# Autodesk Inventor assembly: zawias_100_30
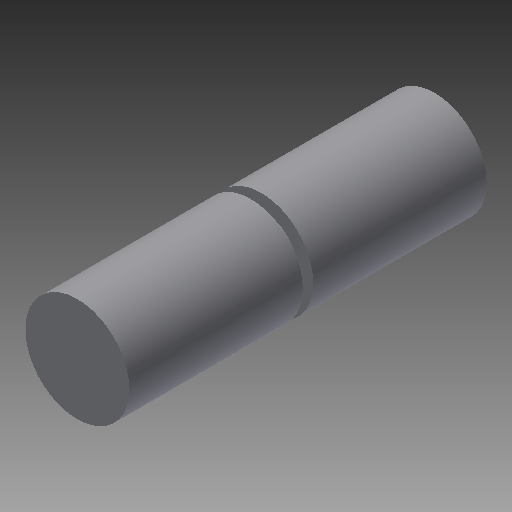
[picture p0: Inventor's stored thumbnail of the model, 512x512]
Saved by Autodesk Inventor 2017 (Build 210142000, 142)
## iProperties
Created: 2020-09
Part Number: zawias_100_30
Document SubType Name: Assembly
Designer: WindowsX
Mass: 68.0469 g
Surface Area: 175.301 cm^2
Volume: 68.0469 cm^3
Density: 1 g/cm^3
Author: WindowsX
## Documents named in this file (3)
- C:\Users\WindowsX\Desktop\brama\zawias_100_30.iam
- C:\Users\WindowsX\Desktop\brama\zawias_dolny.ipt
- C:\Users\WindowsX\Desktop\brama\zawias_gorny.ipt
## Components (2 placed, 2 different names)
1. zawias_dolny:1 — Wstaw:1
2. zawias_gorny:1 — Wstaw:1
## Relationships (1: Insert 1)
- Wstaw:1 [Insert]: zawias_dolny:1 ↔ zawias_gorny:1
